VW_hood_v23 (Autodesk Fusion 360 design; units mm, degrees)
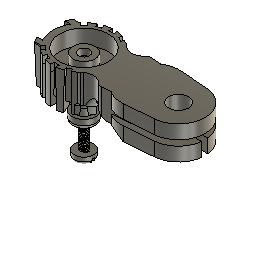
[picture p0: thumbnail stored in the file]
sketch "Sketch1" plane through (0, 0, 0) normal (0, 0, 1) x axis (1, 0, 0)
  line L1 (-15.9441, 0) -> (0, 0)
  line L2 (-10.9223, 7.05) -> (-8.3785, 7.05)
  line L3 (-10.9223, -7.05) -> (-8.3785, -7.05)
  line L4 (-11.979, 5.05) -> (-9.716, 5.05)
  line L5 (-11.979, -5.05) -> (-9.716, -5.05)
  line L6 (46.1591, 0) -> (0, 0)
  line L7 (46.1591, 7.5) -> (7.9783, 7.5)
  line L8 (46.1591, -7.5) -> (7.9783, -7.5)
  line L9 (8.8, 16.1491) -> (8.8, 0)
  line L10 (13.8, 16.1491) -> (13.8, 0)
  line L11 (46.1591, -9.25) -> (0, -9.25)
  line L12 (46.1591, 9.25) -> (0, 9.25)
  line L13 (34.4, 16.1491) -> (34.4, 0)
  line L14 (34.9982, 7.5764) -> (14.3656, 9.2053)
  line L15 (34.9982, -7.5764) -> (14.3656, -9.2053)
  line L16 (0, 4) -> (0, 0)
  line L17 (0, 10.95) -> (0, 8.8)
  line L18 (0.9, 10.913) -> (0.9, 9.9092)
  line L19 (-0.9, 10.913) -> (-0.9, 9.9092)
  line L20 (-5.0077, 9.7378) -> (-4.6236, 8.8105)
  line L21 (-3.3447, 10.4267) -> (-2.9606, 9.4993)
  line L22 (-8.353, 7.0802) -> (-7.6433, 6.3705)
  line L23 (-7.0802, 8.353) -> (-6.3705, 7.6433)
  line L24 (-10.4267, 3.3447) -> (-9.4993, 2.9606)
  line L25 (-9.7378, 5.0077) -> (-8.8105, 4.6236)
  line L26 (-10.913, -0.9) -> (-9.9092, -0.9)
  line L27 (-10.913, 0.9) -> (-9.9092, 0.9)
  line L28 (-9.7378, -5.0077) -> (-8.8105, -4.6236)
  line L29 (-10.4267, -3.3447) -> (-9.4993, -2.9606)
  line L30 (-7.0802, -8.353) -> (-6.3705, -7.6433)
  line L31 (-8.353, -7.0802) -> (-7.6433, -6.3705)
  line L32 (-3.3447, -10.4267) -> (-2.9606, -9.4993)
  line L33 (-5.0077, -9.7378) -> (-4.6236, -8.8105)
  line L34 (0.9, -10.913) -> (0.9, -9.9092)
  line L35 (-0.9, -10.913) -> (-0.9, -9.9092)
  line L36 (5.0077, -9.7378) -> (4.6236, -8.8105)
  line L37 (3.3447, -10.4267) -> (2.9606, -9.4993)
  line L38 (8.353, -7.0802) -> (7.6433, -6.3705)
  line L39 (7.0802, -8.353) -> (6.3705, -7.6433)
  line L40 (10.4267, -3.3447) -> (9.4993, -2.9606)
  line L41 (9.7378, -5.0077) -> (8.8105, -4.6236)
  line L42 (10.913, 0.9) -> (9.9092, 0.9)
  line L43 (10.913, -0.9) -> (9.9092, -0.9)
  line L44 (9.7378, 5.0077) -> (8.8105, 4.6236)
  line L45 (10.4267, 3.3447) -> (9.4993, 2.9606)
  line L46 (7.0802, 8.353) -> (6.3705, 7.6433)
  line L47 (8.353, 7.0802) -> (7.6433, 6.3705)
  line L48 (3.3447, 10.4267) -> (2.9606, 9.4993)
  line L49 (5.0077, 9.7378) -> (4.6236, 8.8105)
  line L50 (41.9277, 1.0459) -> (42, 0)
  line L51 (42, 11.6888) -> (42, 0)
  line L52 (25, 8.3658) -> (25, -8.3658)
  circle C1 centre (0, 0) radius 4
  circle C2 centre (0, 0) radius 1.5
  circle C3 centre (0, 0) radius 8.8
  circle C4 centre (0, 0) radius 10.95
  arc A1 centre (0, 0) radius 13 clockwise from (-10.9223, -7.05) to (-11.979, -5.05)
  arc A2 centre (0, 0) radius 13 clockwise from (-11.979, 5.05) to (-10.9223, 7.05)
  circle C5 centre (34.4, 0) radius 3.6
  circle C6 centre (34.4, 0) radius 7.6
  arc A3 centre (13.8, 26.3873) radius 18.8873 clockwise from (12.0677, 7.5796) to (4.2543, 10.0898)
  arc A4 centre (12.1285, 9.25) radius 1.6715 clockwise from (13.7262, 8.7588) to (11.8654, 7.5993)
  arc A5 centre (14.3319, 8.5725) radius 0.6337 clockwise from (13.7262, 8.7588) to (14.3656, 9.2053)
  arc A6 centre (13.8, -26.3873) radius 18.8873 clockwise from (4.2543, -10.0898) to (12.0677, -7.5796)
  arc A7 centre (12.1285, -9.25) radius 1.6715 clockwise from (11.8654, -7.5993) to (13.7262, -8.7588)
  arc A8 centre (14.3319, -8.5725) radius 0.6337 clockwise from (14.3656, -9.2053) to (13.7262, -8.7588)
  arc A9 centre (0, 0) radius 9.95 clockwise from (-0.9, 9.9092) to (0.9, 9.9092)
  arc A10 centre (0, 0) radius 9.95 clockwise from (-4.6236, 8.8105) to (-2.9606, 9.4993)
  arc A11 centre (0, 0) radius 9.95 clockwise from (-7.6433, 6.3705) to (-6.3705, 7.6433)
  arc A12 centre (0, 0) radius 9.95 clockwise from (-9.4993, 2.9606) to (-8.8105, 4.6236)
  arc A13 centre (0, 0) radius 9.95 clockwise from (-9.9092, -0.9) to (-9.9092, 0.9)
  arc A14 centre (0, 0) radius 9.95 clockwise from (-8.8105, -4.6236) to (-9.4993, -2.9606)
  arc A15 centre (0, 0) radius 9.95 clockwise from (-6.3705, -7.6433) to (-7.6433, -6.3705)
  arc A16 centre (0, 0) radius 9.95 clockwise from (-2.9606, -9.4993) to (-4.6236, -8.8105)
  arc A17 centre (0, 0) radius 9.95 clockwise from (0.9, -9.9092) to (-0.9, -9.9092)
  arc A18 centre (0, 0) radius 9.95 clockwise from (4.6236, -8.8105) to (2.9606, -9.4993)
  arc A19 centre (0, 0) radius 9.95 clockwise from (7.6433, -6.3705) to (6.3705, -7.6433)
  arc A20 centre (0, 0) radius 9.95 clockwise from (9.4993, -2.9606) to (8.8105, -4.6236)
  arc A21 centre (0, 0) radius 9.95 clockwise from (9.9092, 0.9) to (9.9092, -0.9)
  arc A22 centre (0, 0) radius 9.95 clockwise from (8.8105, 4.6236) to (9.4993, 2.9606)
  arc A23 centre (0, 0) radius 9.95 clockwise from (6.3705, 7.6433) to (7.6433, 6.3705)
  arc A24 centre (0, 0) radius 9.95 clockwise from (2.9606, 9.4993) to (4.6236, 8.8105)
  point P1 (0, 0)
  point P2 (0, 0)
  point P3 (0, 0)
  point P5 (0, 0)
  point P6 (0, 0)
  point P8 (-10.9223, 7.05)
  point P13 (-8.3785, 7.05)
  point P14 (-9.716, 5.05)
  point P15 (-9.716, -5.05)
  point P16 (-8.3785, -7.05)
  point P4 (0, 0)
  point P17 (0, 0)
  point P18 (7.9783, 7.5)
  point P19 (7.9783, -7.5)
  point P20 (8.8, 0)
  point P27 (34.4, 0)
  point P29 (34.4, 0)
  point P31 (34.9982, 7.5764)
  point P33 (4.2543, 10.0898)
  point P34 (11.8654, 7.5993)
  point P36 (12.0677, 7.5796)
  point P47 (34.9982, -7.5764)
  point P41 (4.2543, -10.0898)
  point P44 (11.8654, -7.5993)
  point P42 (12.0677, -7.5796)
  point P37 (14.3656, 9.2053)
  point P46 (14.3656, -9.2053)
  point P38 (13.7262, 8.7588)
  point P45 (13.7262, -8.7588)
  point P49 (0, 0)
  point P50 (0, 10.95)
  point P51 (0, 4)
  point P52 (0, 8.8)
  point P53 (-0.9, 10.913)
  point P54 (0.9, 10.913)
  point P138 (42, 0)
  point P139 (41.9277, 1.0459)
  point P141 (25, -8.3658)
  point P142 (25, 8.3658)
  coincident P1 P2
  coincident P1 P3
  concentric C2 C3
  coincident P1 P5
  coincident P1 P6
  horizontal L1
  parallel L1 L2
  coincident P8 A1
  parallel L1 L4
  parallel L1 L5
  parallel L1 L3
  concentric C3 A1
  concentric A1 A2
  coincident C4 P13
  coincident C4 P14
  coincident C4 P15
  coincident C4 P16
  coincident P4 P17
  parallel L1 L6
  coincident C4 P18
  coincident C4 P19
  coincident L6 P20
  coincident C3 P20
  tangent C3 L9
  perpendicular L7 L9
  coincident P27 P29
  concentric C5 C6
  tangent C6 L14
  coincident C6 P31
  tangent L7 A3
  coincident C4 P33
  tangent L10 A4
  coincident A3 P34
  coincident A4 P36
  tangent A4 A5
  symmetric L6 P31 P47
  symmetric L6 P33 P41
  symmetric L6 A3 A6
  symmetric L6 P34 P44
  symmetric L6 A4 A7
  symmetric L6 P36 P42
  symmetric L6 P37 P46
  symmetric L6 P38 P45
  symmetric L6 A5 A8
  coincident P5 P49
  coincident C4 P50
  vertical L16
  coincident C1 P51
  coincident C3 P52
  collinear L16 L17
  parallel L17 L19
  coincident C4 P53
  parallel L17 L18
  coincident C4 P54
  parallel L6 L12
  coincident L6 P138
  coincident C6 P138
  coincident C6 P139
  tangent C6 L51
  perpendicular L7 L51
  parallel L51 L52
  coincident L15 P141
  coincident L14 P142
  dimension "d1" diameter C1 = 8
  dimension "d2" diameter C2 = 3
  dimension "d3" diameter C3 = 17.6
  dimension "d4" diameter C4 = 21.9 (= "22 mm - 0.1 mm")
  dimension "d12" = 5
  dimension "d13" = 9.25 (= "( 18.5 / 2 ) * 1 mm")
  dimension "d15" = 25.6 (= "22 mm + ( ( 7.2 / 2 ) * 1 mm )")
  dimension "d16" diameter C5 = 7.2
  dimension "d17" diameter C6 = 15.2
  dimension "d23" distance L17 L19 = 0.9
  dimension "d24" distance L17 L18 = 0.9
  dimension "d22" C-Pattern1-Angle = 360
sketch "Sketch2" plane through (0, 0, 0) normal (0, 0, 1) x axis (1, 0, 0)
  line L1 (0, 10.95) -> (0, 8.8)
  line L2 (-3.3447, 10.4267) -> (-2.5185, 8.4319)
  line L3 (10.913, 0.9) -> (9.9092, 0.9)
  line L4 (-5.0077, 9.7378) -> (-4.1814, 7.7431)
  line L5 (-11.979, -5.05) -> (-9.716, -5.05)
  line L6 (-10.4267, 3.3447) -> (-9.4993, 2.9606)
  line L7 (-11.979, 5.05) -> (-9.716, 5.05)
  line L8 (-10.9223, -7.05) -> (-8.3785, -7.05)
  line L9 (-10.913, 0.9) -> (-9.9092, 0.9)
  line L10 (46.1591, 0) -> (0, 0)
  line L11 (-8.353, 7.0802) -> (-6.8263, 5.5535)
  line L12 (-10.9223, 7.05) -> (-8.3785, 7.05)
  line L13 (-10.4267, -3.3447) -> (-9.4993, -2.9606)
  line L14 (-8.353, -7.0802) -> (-6.8263, -5.5535)
  line L15 (-9.7378, 5.0077) -> (-8.8105, 4.6236)
  line L16 (-10.913, -0.9) -> (-9.9092, -0.9)
  line L17 (8.353, -7.0802) -> (7.6433, -6.3705)
  line L18 (7.0802, -8.353) -> (6.3705, -7.6433)
  line L19 (5.0077, -9.7378) -> (4.1814, -7.7431)
  line L20 (3.3447, -10.4267) -> (2.5185, -8.4319)
  line L21 (-3.3447, -10.4267) -> (-2.5185, -8.4319)
  line L22 (-0.9, -10.913) -> (-0.9, -8.7539)
  line L23 (0.9, -10.913) -> (0.9, -8.7539)
  line L24 (-5.0077, -9.7378) -> (-4.1814, -7.7431)
  line L25 (9.7378, -5.0077) -> (8.8105, -4.6236)
  line L26 (10.4267, -3.3447) -> (9.4993, -2.9606)
  line L27 (8.8, 16.1491) -> (8.8, 0)
  line L28 (46.1591, -9.25) -> (0, -9.25)
  line L29 (-7.0802, 8.353) -> (-5.5535, 6.8263)
  line L30 (-15.9441, 0) -> (0, 0)
  line L31 (46.1591, -7.5) -> (7.9783, -7.5)
  line L32 (-7.0802, -8.353) -> (-5.5535, -6.8263)
  line L33 (-9.7378, -5.0077) -> (-8.8105, -4.6236)
  line L34 (8.353, 7.0802) -> (7.6433, 6.3705)
  line L35 (7.0802, 8.353) -> (6.3705, 7.6433)
  line L36 (0, 4.35) -> (0, 0)
  line L37 (46.1591, 7.5) -> (7.9783, 7.5)
  line L38 (34.9982, -7.5764) -> (14.3656, -9.2053)
  line L39 (34.4, 16.1491) -> (34.4, 0)
  line L40 (34.9982, 7.5764) -> (14.3656, 9.2053)
  line L41 (13.8, 16.1491) -> (13.8, 0)
  line L42 (0.9, 10.913) -> (0.9, 8.7539)
  line L43 (9.7378, 5.0077) -> (8.8105, 4.6236)
  line L44 (-0.9, 10.913) -> (-0.9, 8.7539)
  line L45 (5.0077, 9.7378) -> (4.1814, 7.7431)
  line L46 (3.3447, 10.4267) -> (2.5185, 8.4319)
  line L47 (10.4267, 3.3447) -> (9.4993, 2.9606)
  line L48 (46.1591, 9.25) -> (0, 9.25)
  line L49 (10.913, -0.9) -> (9.9092, -0.9)
  line L50 (41.92, 1.1) -> (37.8278, 1.1)
  line L51 (41.92, -1.1) -> (37.8278, -1.1)
  line L52 (25, 8.3658) -> (25, -8.3658)
  circle C1 centre (0, 0) radius 1.5
  arc A1 centre (0, 0) radius 9.95 clockwise from (8.8105, 4.6236) to (9.4993, 2.9606)
  arc A2 centre (13.8, 26.3873) radius 18.8873 clockwise from (12.0677, 7.5796) to (4.2543, 10.0898)
  arc A3 centre (0, 0) radius 9.95 clockwise from (9.9092, 0.9) to (9.9092, -0.9)
  arc A4 centre (0, 0) radius 9.95 clockwise from (-7.6433, 6.3705) to (-6.3705, 7.6433)
  circle C2 centre (0, 0) radius 4.35
  arc A5 centre (0, 0) radius 9.95 clockwise from (-8.8105, -4.6236) to (-9.4993, -2.9606)
  arc A6 centre (0, 0) radius 13 clockwise from (-10.9223, -7.05) to (-11.979, -5.05)
  arc A7 centre (0, 0) radius 9.95 clockwise from (-6.3705, -7.6433) to (-7.6433, -6.3705)
  arc A8 centre (13.8, -26.3873) radius 18.8873 clockwise from (4.2543, -10.0898) to (12.0677, -7.5796)
  arc A9 centre (0, 0) radius 9.95 clockwise from (4.6236, -8.8105) to (2.9606, -9.4993)
  arc A10 centre (0, 0) radius 9.95 clockwise from (7.6433, -6.3705) to (6.3705, -7.6433)
  arc A11 centre (0, 0) radius 9.95 clockwise from (0.9, -9.9092) to (-0.9, -9.9092)
  arc A12 centre (0, 0) radius 9.95 clockwise from (-2.9606, -9.4993) to (-4.6236, -8.8105)
  arc A13 centre (0, 0) radius 9.95 clockwise from (9.4993, -2.9606) to (8.8105, -4.6236)
  circle C3 centre (0, 0) radius 10.95
  arc A14 centre (0, 0) radius 9.95 clockwise from (-9.4993, 2.9606) to (-8.8105, 4.6236)
  arc A15 centre (0, 0) radius 9.95 clockwise from (-9.9092, -0.9) to (-9.9092, 0.9)
  arc A16 centre (0, 0) radius 13 clockwise from (-11.979, 5.05) to (-10.9223, 7.05)
  circle C4 centre (0, 0) radius 8.8
  arc A17 centre (0, 0) radius 9.95 clockwise from (2.9606, 9.4993) to (4.6236, 8.8105)
  circle C5 centre (34.4, 0) radius 3.6
  arc A18 centre (14.3319, -8.5725) radius 0.6337 clockwise from (14.3656, -9.2053) to (13.7262, -8.7588)
  arc A19 centre (12.1285, -9.25) radius 1.6715 clockwise from (11.8654, -7.5993) to (13.7262, -8.7588)
  arc A20 centre (14.3319, 8.5725) radius 0.6337 clockwise from (13.7262, 8.7588) to (14.3656, 9.2053)
  arc A21 centre (12.1285, 9.25) radius 1.6715 clockwise from (13.7262, 8.7588) to (11.8654, 7.5993)
  circle C6 centre (34.4, 0) radius 7.6
  arc A22 centre (0, 0) radius 9.95 clockwise from (-4.6236, 8.8105) to (-2.9606, 9.4993)
  arc A23 centre (0, 0) radius 9.95 clockwise from (-0.9, 9.9092) to (0.9, 9.9092)
  arc A24 centre (0, 0) radius 9.95 clockwise from (6.3705, 7.6433) to (7.6433, 6.3705)
  circle C7 centre (0, 0) radius 2.5
  circle C8 centre (0, 0) radius 3
  point P24 (0, 0)
  point P29 (0, 0)
  point P41 (0, 0)
  point P33 (0, 0)
  point P45 (0, 0)
  point P46 (-10.9223, 7.05)
  point P42 (-8.3785, 7.05)
  point P21 (-9.716, 5.05)
  point P34 (-9.716, -5.05)
  point P39 (-8.3785, -7.05)
  point P26 (0, 0)
  point P38 (0, 0)
  point P31 (7.9783, 7.5)
  point P44 (7.9783, -7.5)
  point P40 (8.8, 0)
  point P37 (34.4, 0)
  point P48 (34.4, 0)
  point P50 (34.9982, 7.5764)
  point P53 (4.2543, 10.0898)
  point P20 (11.8654, 7.5993)
  point P52 (12.0677, 7.5796)
  point P85 (34.9982, -7.5764)
  point P61 (4.2543, -10.0898)
  point P80 (11.8654, -7.5993)
  point P49 (12.0677, -7.5796)
  point P54 (14.3656, 9.2053)
  point P81 (14.3656, -9.2053)
  point P56 (13.7262, 8.7588)
  point P84 (13.7262, -8.7588)
  point P59 (0, 0)
  point P60 (0, 10.95)
  point P107 (0, 4.35)
  point P92 (0, 8.8)
  point P103 (-0.9, 10.913)
  point P98 (0.9, 10.913)
  point P139 (0, 0)
  point P141 (41.92, 1.1)
  point P142 (41.92, -1.1)
  point P143 (37.8278, 1.1)
  point P144 (37.8278, -1.1)
  point P147 (-4.1814, 7.7431)
  point P75 (-4.6236, 8.8105)
  point P109 (-2.9606, 9.4993)
  point P148 (-6.8263, 5.5535)
  point P100 (-7.6433, 6.3705)
  point P66 (-6.3705, 7.6433)
  point P149 (-5.5535, 6.8263)
  point P150 (-2.5185, 8.4319)
  point P101 (-0.9, 9.9092)
  point P97 (0.9, 9.9092)
  point P151 (0.9, 8.7539)
  point P152 (-0.9, 8.7539)
  point P3 (2.9606, 9.4993)
  point P153 (2.5185, 8.4319)
  point P154 (4.1814, 7.7431)
  point P2 (4.6236, 8.8105)
  point P118 (2.9606, -9.4993)
  point P155 (2.5185, -8.4319)
  point P156 (4.1814, -7.7431)
  point P116 (4.6236, -8.8105)
  point P91 (0.9, -9.9092)
  point P157 (0.9, -8.7539)
  point P115 (-0.9, -9.9092)
  point P158 (-0.9, -8.7539)
  point P89 (-2.9606, -9.4993)
  point P159 (-2.5185, -8.4319)
  point P160 (-4.1814, -7.7431)
  point P65 (-4.6236, -8.8105)
  point P79 (-6.3705, -7.6433)
  point P161 (-5.5535, -6.8263)
  point P162 (-6.8263, -5.5535)
  point P83 (-7.6433, -6.3705)
  coincident P24 P29
  coincident P24 P41
  concentric C1 C4
  coincident P24 P33
  coincident P24 P45
  horizontal L30
  parallel L12 L30
  coincident P46 A6
  parallel L7 L30
  parallel L5 L30
  parallel L8 L30
  concentric A6 C4
  concentric A6 A16
  coincident P42 C3
  coincident P21 C3
  coincident P34 C3
  coincident P39 C3
  coincident P26 P38
  parallel L10 L30
  coincident P31 C3
  coincident P44 C3
  coincident P40 L10
  coincident P40 C4
  tangent L27 C4
  perpendicular L27 L37
  coincident P37 P48
  concentric C5 C6
  tangent L40 C6
  coincident P50 C6
  tangent A2 L37
  coincident P53 C3
  tangent A21 L41
  coincident P20 A2
  coincident P52 A21
  tangent A20 A21
  symmetric P50 P85 L10
  symmetric P53 P61 L10
  symmetric A2 L10 A8
  symmetric P20 P80 L10
  symmetric L10 A19 A21
  symmetric P49 P52 L10
  symmetric P54 P81 L10
  symmetric P56 P84 L10
  symmetric L10 A18 A20
  coincident P33 P59
  coincident P60 C3
  vertical L36
  coincident P107 C2
  coincident P92 C4
  collinear L1 L36
  parallel L1 L44
  coincident P103 C3
  parallel L1 L42
  coincident P98 C3
  parallel L10 L48
  coincident P24 P139
  concentric A5 C8
  coincident C6 P141
  coincident C6 P142
  coincident C5 P143
  coincident C5 P144
  coincident C4 P147
  coincident P75 L4
  coincident P109 L2
  coincident C4 P148
  coincident P100 L11
  coincident P66 L29
  coincident C4 P149
  coincident C4 P150
  coincident P101 L44
  coincident P97 L42
  coincident C4 P151
  coincident C4 P152
  coincident P3 L46
  coincident C4 P153
  coincident C4 P154
  coincident P2 L45
  coincident P118 L20
  coincident C4 P155
  coincident C4 P156
  coincident P116 L19
  coincident P91 L23
  coincident C4 P157
  coincident P115 L22
  coincident C4 P158
  coincident P89 L21
  coincident C4 P159
  coincident C4 P160
  coincident P65 L24
  coincident P79 L32
  coincident C4 P161
  coincident C4 P162
  coincident P83 L14
  dimension "d25" = 5
  dimension "d26" = 9.25 (= "( 18.5 / 2 ) * 1 mm")
  dimension "d27" = 25.6 (= "22 mm + ( ( 7.2 / 2 ) * 1 mm )")
  dimension "d30" diameter C2 = 8.7
  dimension "d31" diameter C1 = 3
  dimension "d32" diameter C4 = 17.6
  dimension "d33" diameter C3 = 21.9 (= "22 mm - 0.1 mm")
  dimension "d34" diameter C5 = 7.2
  dimension "d35" diameter C6 = 15.2
  dimension "d36" distance L1 L44 = 0.9
  dimension "d37" distance L1 L42 = 0.9
  dimension "d38" diameter C7 = 5
  dimension "d39" diameter C8 = 6
extrude "Extrude1" new body sketch "Sketch1" profile of C3 C4 A3 A6 L18 L19 A9 L20 A10 L21 L22 A11 L23 L30 A15 L31 L32 A16 L33 L34 A17 L35 L36 A18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 along normal blind 9.5
extrude "Extrude2" add sketch "Sketch1" profile of C1 C2 C3 along normal blind 4.4
extrude "Extrude3" sketch "Sketch1" profile of C1 C2 blind 4.2
extrude "Extrude4" sketch "Sketch1" profile of C5 C6 L14 L15 L52 blind -10
extrude "Extrude5" sketch "Sketch1" profile of C4 L14 A3 A4 A5 A6 A7 L15 A8 L52 blind -8
extrude "Extrude6" new body sketch "Sketch2" profile of L2 L4 A2 A4 L11 L14 A7 A8 L19 A9 L20 A11 L21 L22 L23 A12 L24 L29 C3 L32 C4 A17 A22 A23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 against normal blind 3.5
extrude "Extrude7" new body sketch "Sketch2" profile of C1 C2 C7 C8 against normal blind 7
extrude "Extrude8" sketch "Sketch2" profile of C1 C7 C8 blind -3
extrude "Extrude9" sketch "Sketch2" profile of C1 C2 C7 C8 blind -7.5 (= "-2.5 mm - 5 mm")
chamfer "Chamfer1" distance 1.5 distance 5
move "Move1"
combine "Combine1"
offset_faces "OffsetFaces1" distance -1.5
extrude "Extrude10" sketch "Sketch1" profile of C4 L2 L3 A2 L4 L5 blind -14.5
chamfer "Chamfer3" distance 1.5 distance 14.5
chamfer "Chamfer4" distance 1.5 distance 14.5
combine "Combine2"
extrude "Extrude11" cut of existing geometry blind -0.1
chamfer "Chamfer2" distance 2 distance 0.5
fillet "Fillet1" radius 10
fillet "Fillet2" radius 2
sketch "Sketch3" plane through (0, 0, 0) normal (0, 0, 1) x axis (1, 0, 0)
  line L1 (46.1591, 0) -> (0, 0)
  line L2 (34.9982, 7.5764) -> (25, 8.3658)
  line L3 (34.9982, -7.5764) -> (25, -8.3658)
  line L4 (41.9524, 0.8491) -> (42, 0)
  line L5 (41.9524, 0.8491) -> (42, 0)
  line L6 (42, 13.1287) -> (42, 0)
  line L7 (32.5, 13.1287) -> (32.5, -3.0578)
  line L8 (32.5, 3.0578) -> (25, 8.3658)
  line L9 (32.5, -3.0578) -> (25, -8.3658)
  arc A1 centre (34.4, 0) radius 7.6 clockwise from (34.9982, 7.5764) to (34.9982, -7.5764)
  arc A2 centre (34.4, 0) radius 3.6 clockwise from (32.5, 3.0578) to (32.5, -3.0578)
  point P6 (34.9982, 7.5764)
  point P7 (34.9982, -7.5764)
  point P10 (42, 0)
  point P11 (41.9524, 0.8491)
  point P15 (32.5, 3.0578)
  concentric A1 A2
  tangent L2 A1
  symmetric P6 P7 L1
  coincident L1 P10
  coincident P10 A1
  coincident P11 A1
  parallel L4 L5
  tangent L6 A1
  perpendicular L1 L6
  parallel L6 L7
  coincident L7 P15
  dimension "d78" diameter A2 = 7.2
  dimension "d79" diameter A1 = 15.2
extrude "Extrude12" sketch "Sketch3" profile of A1 A2 L2 L3 L8 L9 blind -2 from offset -4.5
extrude "Extrude13" sketch "Sketch2" profile of C5 C6 L51 L50 blind -5
extrude "Extrude14" sketch "Sketch2" profile of L2 L4 A2 A4 L11 L14 A7 A8 L19 A9 L20 A11 L21 L22 L23 A12 L24 L29 C3 L32 C4 A17 A22 A23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 blind 3
sketch "Sketch4" plane through (0, 0, 0) normal (0, 0, 1) x axis (1, 0, 0)
  line L1 (-3.3447, 10.4267) -> (-1.9022, 6.9442)
  line L2 (10.913, 0.9) -> (7.1435, 0.9)
  line L3 (8.8, 16.1491) -> (8.8, 0)
  line L4 (0, 4) -> (0, 0)
  line L5 (-10.4267, 3.3447) -> (-9.4993, 2.9606)
  line L6 (-10.4267, -3.3447) -> (-9.4993, -2.9606)
  line L7 (-9.7378, 5.0077) -> (-8.8105, 4.6236)
  line L8 (-11.979, 5.05) -> (-9.716, 5.05)
  line L9 (-8.353, 7.0802) -> (-5.6876, 4.4148)
  line L10 (-10.9223, 7.05) -> (-8.3785, 7.05)
  line L11 (-10.913, -0.9) -> (-9.9092, -0.9)
  line L12 (-7.0802, 8.353) -> (-4.4148, 5.6876)
  line L13 (-11.979, -5.05) -> (-9.716, -5.05)
  line L14 (-8.353, -7.0802) -> (-5.6876, -4.4148)
  line L15 (-10.913, 0.9) -> (-9.9092, 0.9)
  line L16 (-9.7378, -5.0077) -> (-8.8105, -4.6236)
  line L17 (-10.9223, -7.05) -> (-8.3785, -7.05)
  line L18 (-7.0802, -8.353) -> (-4.4148, -5.6876)
  line L19 (46.1591, 0) -> (0, 0)
  line L20 (46.1591, -9.25) -> (0, -9.25)
  line L21 (46.1591, -7.5) -> (7.9783, -7.5)
  line L22 (46.1591, 9.25) -> (0, 9.25)
  line L23 (-15.9441, 0) -> (0, 0)
  line L24 (0, 10.95) -> (0, 8.8)
  line L25 (-0.9, 10.913) -> (-0.9, 7.1435)
  line L26 (10.4267, 3.3447) -> (6.9442, 1.9022)
  line L27 (0.9, 10.913) -> (0.9, 7.1435)
  line L28 (8.353, 7.0802) -> (5.6876, 4.4148)
  line L29 (42, 11.6888) -> (42, 0)
  line L30 (5.0077, 9.7378) -> (3.5652, 6.2553)
  line L31 (46.1591, 7.5) -> (7.9783, 7.5)
  line L32 (9.7378, -5.0077) -> (6.2553, -3.5652)
  line L33 (0.9, -10.913) -> (0.9, -7.1435)
  line L34 (7.0802, -8.353) -> (4.4148, -5.6876)
  line L35 (8.353, -7.0802) -> (5.6876, -4.4148)
  line L36 (7.0802, 8.353) -> (4.4148, 5.6876)
  line L37 (41.9277, 1.0459) -> (42, 0)
  line L38 (34.4, 16.1491) -> (34.4, 0)
  line L39 (25, 8.3658) -> (25, -8.3658)
  line L40 (34.9982, -7.5764) -> (14.3656, -9.2053)
  line L41 (34.9982, 7.5764) -> (14.2372, 9.2155)
  line L42 (5.0077, -9.7378) -> (3.5652, -6.2553)
  line L43 (-0.9, -10.913) -> (-0.9, -7.1435)
  line L44 (-3.3447, -10.4267) -> (-1.9022, -6.9442)
  line L45 (-5.0077, -9.7378) -> (-3.5652, -6.2553)
  line L46 (3.3447, -10.4267) -> (1.9022, -6.9442)
  line L47 (10.4267, -3.3447) -> (6.9442, -1.9022)
  line L48 (10.913, -0.9) -> (7.1435, -0.9)
  line L49 (-5.0077, 9.7378) -> (-3.5652, 6.2553)
  line L50 (9.7378, 5.0077) -> (6.2553, 3.5652)
  line L51 (3.3447, 10.4267) -> (1.9022, 6.9442)
  arc A1 centre (0, 0) radius 13 clockwise from (-10.9223, -7.05) to (-11.979, -5.05)
  arc A2 centre (0, 0) radius 9.95 clockwise from (-8.8105, -4.6236) to (-9.4993, -2.9606)
  arc A3 centre (0, 0) radius 9.95 clockwise from (-9.4993, 2.9606) to (-8.8105, 4.6236)
  circle C1 centre (0, 0) radius 8.8
  arc A4 centre (13.8, -26.3873) radius 18.8873 clockwise from (4.2543, -10.0898) to (12.0677, -7.5796)
  arc A5 centre (13.8, 26.3873) radius 18.8873 clockwise from (12.0677, 7.5796) to (4.2543, 10.0898)
  circle C2 centre (0, 0) radius 10.95
  arc A6 centre (12.1285, -9.25) radius 1.6715 clockwise from (11.8654, -7.5993) to (13.7262, -8.7588)
  circle C3 centre (0, 0) radius 1.5
  circle C4 centre (34.4, 0) radius 7.6
  circle C5 centre (0, 0) radius 4
  arc A7 centre (0, 0) radius 9.95 clockwise from (-9.9092, -0.9) to (-9.9092, 0.9)
  arc A8 centre (0, 0) radius 13 clockwise from (-11.979, 5.05) to (-10.9223, 7.05)
  circle C6 centre (34.4, 0) radius 3.6
  arc A9 centre (12.1285, 9.25) radius 1.6715 clockwise from (13.7262, 8.7588) to (11.8654, 7.5993)
  arc A10 centre (14.3319, -8.5725) radius 0.6337 clockwise from (14.3656, -9.2053) to (13.7262, -8.7588)
  arc A11 centre (14.3319, 8.5725) radius 0.6337 clockwise from (13.7262, 8.7588) to (14.3656, 9.2053)
  circle C7 centre (10.333, 11.4626) radius 4.5
  circle C8 centre (10.333, -11.4626) radius 4.5
  circle C9 centre (0, 0) radius 7.2
  point P18 (0, 0)
  point P22 (0, 0)
  point P34 (0, 0)
  point P26 (0, 0)
  point P37 (0, 0)
  point P38 (-10.9223, 7.05)
  point P35 (-8.3785, 7.05)
  point P15 (-9.716, 5.05)
  point P27 (-9.716, -5.05)
  point P32 (-8.3785, -7.05)
  point P19 (0, 0)
  point P31 (0, 0)
  point P24 (7.9783, 7.5)
  point P36 (7.9783, -7.5)
  point P33 (8.8, 0)
  point P30 (34.4, 0)
  point P40 (34.4, 0)
  point P42 (34.9982, 7.5764)
  point P45 (4.2543, 10.0898)
  point P14 (11.8654, 7.5993)
  point P44 (12.0677, 7.5796)
  point P70 (34.9982, -7.5764)
  point P53 (4.2543, -10.0898)
  point P67 (11.8654, -7.5993)
  point P41 (12.0677, -7.5796)
  point P46 (14.3656, 9.2053)
  point P68 (14.3656, -9.2053)
  point P48 (13.7262, 8.7588)
  point P69 (13.7262, -8.7588)
  point P51 (0, 0)
  point P52 (0, 10.95)
  point P85 (0, 4)
  point P74 (0, 8.8)
  point P82 (-0.9, 10.913)
  point P79 (0.9, 10.913)
  point P101 (42, 0)
  point P99 (41.9277, 1.0459)
  point P102 (25, -8.3658)
  point P100 (25, 8.3658)
  point P9 (7.0802, 8.353)
  point P107 (-5.6876, 4.4148)
  point P108 (-4.4148, 5.6876)
  point P109 (-3.5652, 6.2553)
  point P110 (-0.9, 7.1435)
  point P111 (0.9, 7.1435)
  point P112 (1.9022, 6.9442)
  point P113 (3.5652, 6.2553)
  point P114 (4.4148, 5.6876)
  point P115 (5.6876, 4.4148)
  point P116 (6.2553, 3.5652)
  point P117 (6.9442, 1.9022)
  point P118 (7.1435, 0.9)
  point P119 (7.1435, -0.9)
  point P120 (6.9442, -1.9022)
  point P121 (6.2553, -3.5652)
  point P122 (5.6876, -4.4148)
  point P123 (4.4148, -5.6876)
  point P124 (3.5652, -6.2553)
  point P125 (1.9022, -6.9442)
  point P126 (0.9, -7.1435)
  point P127 (-0.9, -7.1435)
  point P128 (-1.9022, -6.9442)
  point P129 (-3.5652, -6.2553)
  point P130 (-4.4148, -5.6876)
  point P131 (-5.6876, -4.4148)
  point P132 (-1.9022, 6.9442)
  coincident P18 P22
  coincident P18 P34
  concentric C1 C3
  coincident P18 P26
  coincident P18 P37
  horizontal L23
  parallel L10 L23
  coincident P38 A1
  parallel L8 L23
  parallel L13 L23
  parallel L17 L23
  concentric A1 C1
  concentric A1 A8
  coincident P35 C2
  coincident P15 C2
  coincident P27 C2
  coincident P32 C2
  coincident P19 P31
  parallel L19 L23
  coincident P24 C2
  coincident P36 C2
  coincident P33 L19
  coincident P33 C1
  tangent L3 C1
  perpendicular L3 L31
  coincident P30 P40
  concentric C4 C6
  tangent C4 L41
  coincident P42 C4
  tangent A5 L31
  coincident P45 C2
  coincident P14 A5
  coincident P44 A9
  tangent A9 A11
  symmetric P42 P70 L19
  symmetric P45 P53 L19
  symmetric L19 A4 A5
  symmetric P14 P67 L19
  symmetric L19 A6 A9
  symmetric P41 P44 L19
  symmetric P46 P68 L19
  symmetric P48 P69 L19
  symmetric L19 A10 A11
  coincident P26 P51
  coincident P52 C2
  vertical L4
  coincident P85 C5
  coincident P74 C1
  collinear L4 L24
  parallel L24 L25
  coincident P82 C2
  parallel L24 L27
  coincident P79 C2
  parallel L19 L22
  coincident P101 L19
  coincident P101 C4
  coincident P99 C4
  tangent L29 C4
  perpendicular L29 L31
  parallel L29 L39
  coincident P102 L40
  coincident P100 L41
  coincident P46 L41
  coincident P9 C7
  symmetric L19 C7 C8
  concentric C2 C9
  coincident C9 P107
  coincident C9 P108
  coincident C9 P109
  coincident C9 P110
  coincident C9 P111
  coincident C9 P112
  coincident C9 P113
  coincident C9 P114
  coincident C9 P115
  coincident C9 P116
  coincident C9 P117
  coincident C9 P118
  coincident C9 P119
  coincident C9 P120
  coincident C9 P121
  coincident C9 P122
  coincident C9 P123
  coincident C9 P124
  coincident C9 P125
  coincident C9 P126
  coincident C9 P127
  coincident C9 P128
  coincident C9 P129
  coincident C9 P130
  coincident C9 P131
  coincident C9 P132
  dimension "d98" = 5
  dimension "d99" = 9.25 (= "( 18.5 / 2 ) * 1 mm")
  dimension "d100" = 25.6 (= "22 mm + ( ( 7.2 / 2 ) * 1 mm )")
  dimension "d103" diameter C5 = 8
  dimension "d104" diameter C3 = 3
  dimension "d105" diameter C1 = 17.6
  dimension "d106" diameter C2 = 21.9 (= "22 mm - 0.1 mm")
  dimension "d107" diameter C6 = 7.2
  dimension "d108" diameter C4 = 15.2
  dimension "d109" distance L24 L25 = 0.9
  dimension "d110" distance L24 L27 = 0.9
  dimension "d114" diameter C7 = 9
  dimension "d122" diameter C2 = 21.9
  dimension "d133" diameter C9 = 14.4
extrude "Extrude16" cut sketch "Sketch4" profile of C2 C7 C8 distance 20
extrude "Extrude18" sketch "Sketch4" profile of L2 C1 C2 L26 L28 L32 L34 L35 L36 L42 L46 L47 L48 L50 C7 C8 blind 3
extrude "Extrude21" sketch "Sketch4" profile of L1 L2 L9 L12 L14 L18 C1 L25 L26 L27 L28 L30 L32 L33 L34 L35 L36 L42 L43 L44 L45 L46 L47 L48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 blind -2
extrude "Extrude22" sketch "Sketch4" profile of L1 L2 L9 L12 L14 L18 C1 L25 L26 L27 L28 L30 L32 L33 L34 L35 L36 L42 L43 L44 L45 L46 L47 L48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 blind -3
chamfer "Chamfer6" distance 0.2 distance 11
chamfer "Chamfer7" distance 0.2 distance 3
fillet "Fillet3" radius 2
fillet "Fillet4" radius 2
fillet "Fillet5" radius 3
offset_faces "OffsetFaces2" distance 1
offset_faces "OffsetFaces3" distance 1
extrude "Extrude19" cut of existing geometry blind -0.5
copy_paste_bodies "CopyPasteBodies1"
offset_faces "OffsetFaces4" distance 1.5
extrude "Extruir23" of existing geometry blind -0.5
delete_face "DeleteFace2"
extrude "Extruir24" add of existing geometry blind 0.5
offset_faces "OffsetFaces5" distance -4
sketch "Boceto" plane through (0, 0, 0) normal (0, 0, 1) x axis (1, 0, 0)
  line L1 (37.8278, 1.1) -> (41.92, 1.1)
  line L2 (41.92, -1.1) -> (37.8278, -1.1)
  line L3 (24.4772, -8.407) -> (34.9982, -7.5764)
  line L4 (24.4772, 8.407) -> (24.4772, -8.407)
  line L5 (34.9982, 7.5764) -> (24.4772, 8.407)
  line L6 (32.5, -3.0578) -> (25, -8.3658)
  line L7 (25, 8.3658) -> (32.5, 3.0578)
  line L8 (34.9982, 7.5764) -> (25, 8.3658)
  line L9 (25, -8.3658) -> (34.9982, -7.5764)
  line L10 (19, -8.8395) -> (24.4772, -8.407)
  line L11 (19, 8.8395) -> (19, -8.8395)
  line L12 (19, 8.8395) -> (24.4772, 8.407)
  line L13 (24.4772, -8.407) -> (24.4772, 8.407)
  line L14 (19, 8.8395) -> (17.405, 8.9654)
  line L15 (19, -8.8395) -> (19, 8.8395)
  line L16 (17.405, -8.9654) -> (19, -8.8395)
  curve K1 (12.9031, -7.7688) -> (13.4185, -8.187)
  line L17 (12.2463, -4.2108) -> (11.481, -7.1115)
  line L18 (15.3399, -9.1284) -> (17.405, -8.9654)
  curve K2 (13.6903, -8.4663) -> (15.3399, -9.1284)
  line L19 (17.405, 8.9654) -> (15.3399, 9.1284)
  line L20 (11.481, 7.1115) -> (12.2463, 4.2108)
  curve K3 (13.4185, 8.187) -> (12.9031, 7.7688)
  curve K4 (15.3399, 9.1284) -> (13.6903, 8.4663)
  line L21 (17.2196, -10.9863) -> (24.6346, -10.4008)
  line L22 (17.2196, 10.9863) -> (24.6346, 10.4008)
  line L23 (24.6346, -10.4008) -> (35.1556, -9.5702)
  line L24 (35.1556, 9.5702) -> (24.6346, 10.4008)
  line L25 (44, -1.1) -> (41.92, -1.1)
  line L26 (44, 1.1) -> (41.92, 1.1)
  line L27 (19, 10.8457) -> (19, 8.8395)
  line L28 (24.4772, 10.4133) -> (24.4772, 8.407)
  line L29 (19.0232, -9.1339) -> (19, -8.8395)
  line L30 (18.9907, -10.8464) -> (19.0232, -9.1339)
  line L31 (24.4772, -8.6233) -> (24.4772, -8.407)
  line L32 (24.4772, -10.4133) -> (24.4772, -8.6233)
  line L33 (3.4641, -0.5) -> (-3.4641, -0.5)
  line L34 (-3.4641, 0.5) -> (3.4641, 0.5)
  arc A1 centre (34.4, 0) radius 3.6 clockwise from (37.8278, -1.1) to (37.8278, 1.1)
  arc A2 centre (34.4, 0) radius 7.6 clockwise from (41.92, -1.1) to (34.9982, -7.5764)
  arc A3 centre (34.4, 0) radius 7.6 clockwise from (34.9982, 7.5764) to (41.92, 1.1)
  arc A4 centre (34.4, 0) radius 3.6 clockwise from (32.5, 3.0578) to (32.5, -3.0578)
  arc A5 centre (34.4, 0) radius 7.6 clockwise from (34.9982, 7.5764) to (34.9982, -7.5764)
  arc A6 centre (10.333, 11.4626) radius 7.5 clockwise from (17.405, 8.9654) to (12.2463, 4.2108)
  arc A7 centre (10.333, -11.4626) radius 7.5 clockwise from (12.2463, -4.2108) to (17.405, -8.9654)
  arc A8 centre (0, 0) radius 12.95 clockwise from (12.2463, 4.2108) to (12.2463, -4.2108)
  arc A9 centre (10.333, -11.4626) radius 4.5 clockwise from (11.481, -7.1115) to (12.9031, -7.7688)
  arc A10 centre (10.333, -11.4626) radius 7.5 clockwise from (12.2463, -4.2108) to (17.405, -8.9654)
  arc A11 centre (10.333, -11.4626) radius 4.5 clockwise from (13.4185, -8.187) to (13.6903, -8.4663)
  arc A12 centre (10.333, 11.4626) radius 7.5 clockwise from (17.405, 8.9654) to (12.2463, 4.2108)
  arc A13 centre (10.333, 11.4626) radius 4.5 clockwise from (12.9031, 7.7688) to (11.481, 7.1115)
  arc A14 centre (10.333, 11.4626) radius 4.5 clockwise from (13.6903, 8.4663) to (13.4185, 8.187)
  arc A15 centre (34.4, 0) radius 9.6 clockwise from (35.1556, 9.5702) to (35.1556, -9.5702)
  arc A16 centre (10.333, -11.4626) radius 4.5 clockwise from (11.481, -7.1115) to (14.3233, -9.3824)
  arc A17 centre (10.333, 11.4626) radius 4.5 clockwise from (14.3233, 9.3824) to (11.481, 7.1115)
  arc A18 centre (16.9835, 7.9956) radius 3 clockwise from (14.3233, 9.3824) to (17.2196, 10.9863)
  arc A19 centre (16.9835, -7.9956) radius 3 clockwise from (17.2196, -10.9863) to (14.3233, -9.3824)
  circle C1 centre (0, 0) radius 1.5
  circle C2 centre (0, 0) radius 3.5
  point P33 (11.481, -7.1115)
  point P57 (11.481, -7.1115)
  point P29 (10.333, -11.4626)
  point P56 (10.333, -11.4626)
  point P43 (11.481, 7.1115)
  point P59 (11.481, 7.1115)
  point P6 (41.92, -1.1)
  point P66 (41.92, -1.1)
  point P2 (41.92, 1.1)
  point P68 (41.92, 1.1)
  point P20 (19, 8.8395)
  point P70 (19, 8.8395)
  point P9 (24.4772, 8.407)
  point P71 (24.4772, 8.407)
  point P72 (19, 10.8457)
  point P73 (24.4772, 10.4133)
  point P19 (19, -8.8395)
  point P74 (19, -8.8395)
  point P18 (24.4772, -8.407)
  point P76 (24.4772, -8.407)
  point P78 (18.9907, -10.8464)
  point P79 (24.4772, -10.4133)
  point P82 (-3.4641, -0.5)
  point P83 (-3.4641, 0.5)
  point P84 (3.4641, 0.5)
  point P85 (3.4641, -0.5)
  coincident P33 P57
  coincident P29 P56
  parallel L10 L21
  coincident P43 P59
  parallel L12 L22
  tangent A17 A18
  tangent L22 A18
  tangent A16 A19
  tangent L21 A19
  coincident P6 P66
  parallel L2 L25
  coincident P2 P68
  parallel L1 L26
  coincident P20 P70
  vertical L27
  coincident P9 P71
  parallel L13 L28
  coincident L22 P72
  coincident L22 P73
  coincident P19 P74
  perpendicular L10 L29
  coincident P18 P76
  parallel L4 L32
  coincident L21 P78
  coincident L21 P79
  concentric A8 C1
  concentric C1 C2
  horizontal L33
  horizontal L34
  coincident C2 P82
  coincident C2 P83
  coincident C2 P84
  coincident C2 P85
  dimension "d158" = -2
  dimension "d159" = -2
  dimension "d160" = 2
  dimension "d161" radius A18 = 3
  dimension "d162" radius A19 = 3
  dimension "d182" diameter C1 = 3
  dimension "d183" diameter C2 = 7
extrude "Extruir25" sketch "Boceto" profile of A2 L3 L5 A3 L8 A5 L9 L10 L12 L21 L22 L23 L24 A15 L25 L26 L27 L28 L29 L30 L31 L32 blind 3
extrude "Extruir26" sketch "Boceto" profile of A2 L3 L5 A3 L8 A5 L9 L10 L12 L21 L22 L23 L24 A15 L25 L26 L27 L28 L29 L30 L31 L32 blind -5
extrude "Extruir27" sketch "Boceto" profile of A2 L3 L5 A3 L8 A5 L9 L21 L22 L23 L24 A15 L25 L26 L28 L31 L32 blind 2
combine "Combinar3"
extrude "Extruir28" add of existing geometry blind 2
extrude "Extruir29" add of existing geometry blind 2
fillet "Empalme6" radius 10 10
extrude "Extruir30" new body sketch "Boceto" profile of C1 L33 L34 along normal blind 8 bodies "tornillo"
extrude "Extruir31" new body sketch "Boceto" profile of C1 C2 L33 L34 against normal blind 1
extrude "Extruir32" sketch "Boceto" profile of C1 C2 L33 L34 blind -1.5
thread "Rosca"
combine "Combinar4"
fillet "Empalme7" radius 1
combine "Combinar6"
offset_faces "OffsetFaces7" distance 1
combine "Combinar7"
move "Desplazar"
delete_face "DeleteFace3"
delete_face "DeleteFace4"
offset_faces "OffsetFaces8" distance 0.25
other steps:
base_feature "Elemento base" bodies "custom"
named bodies: "original", "custom", "tornillo"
